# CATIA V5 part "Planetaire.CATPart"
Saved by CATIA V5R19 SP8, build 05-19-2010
Part number: Planetaire
Bounding box of the stored display mesh (mm): x 0 to 14, y -15 to 15, z -15 to 15
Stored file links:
  G:\EU_thinkMotion\CFAO_2010\SIL_groupe2\SIL_groupe2\msauret\Brevet_Sauret_parametre\Planetaire.CATPart
  F:\Brevet_Sauret paramétré\Product3.CATProduct
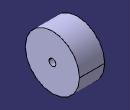
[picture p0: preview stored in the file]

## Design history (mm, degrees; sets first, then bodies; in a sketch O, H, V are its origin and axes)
Set1
  Plane1: linked copy from another document
  Plane2: linked copy from another document
  Point1: linked copy from another document
Body1 (main body)
  Sketch1 on Plane1, origin (0, 0, 0), H (0, 1, 0), V (0, 0, 1)
    circle A1 centre (0, 0) radius 15
  Pad1: profile Sketch1, direction (1, 0, 0), up to Plane2
  Sketch2 on Plane1, origin (0, 0, 0), H (0, 1, 0), V (0, 0, 1)
    circle A1 centre (0, 0) radius 2
    point P1 (0, 0)
    reference projected point E1 (0, 0) from Point1
    distance P1 E1 = 0
    coincidence: P1 V
  Pocket1: profile Sketch2, direction (-1, 0, 0), up to Plane2
  Plane3: type Offset, RefPlane yz-plane, Offset 9
  Sketch3 on Plane3, origin (9, 0, 0), H (0, 1, 0), V (0, 0, 1)
    circle A1 centre (0, 0) radius 15
    reference projected circle E1 centre (0, 0) radius 15 from edge [face of Pad1 from Sketch1.A1 | end face of Pad1]
    coincidence: A1 E1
